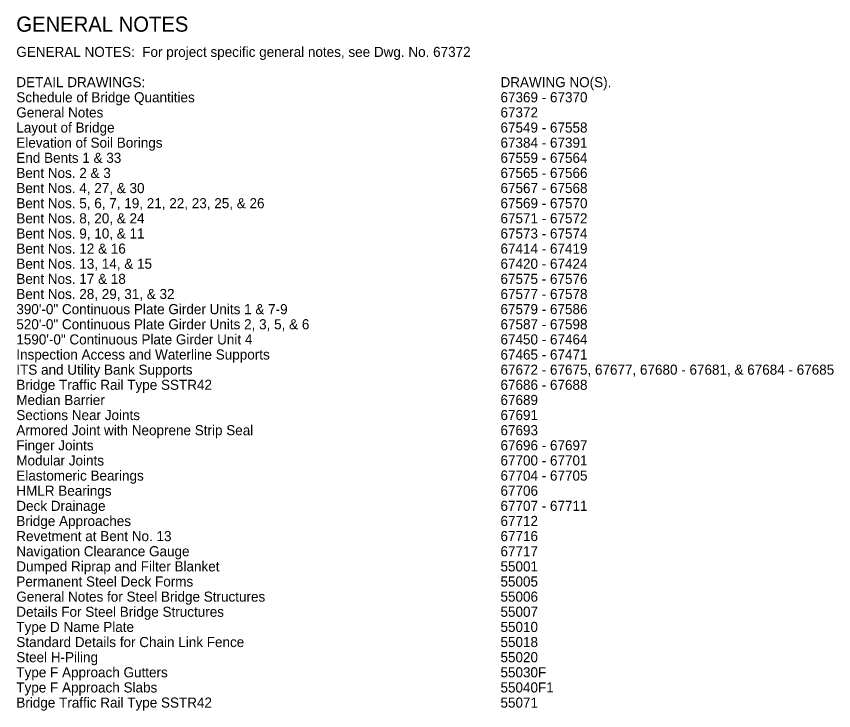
# Model space of a CAD drawing. Extents: x 0.06 to 1.36, y 0.04 to 0.87.
# Drawn here: x 0.0907 to 0.4959, y 0.5215 to 0.8656 of the extents above; entities that cross this region are included whole.
import ezdxf

# ---------------------------------------------------------------- set-up
doc = ezdxf.new("R2010")
doc.units = 0
doc.layers.add('B_Boring Annot', color=7, linetype='Continuous')
doc.layers.add('R_ROW', color=7, linetype='Continuous')

msp = doc.modelspace()

# ---------------------------------------------------------------- texts
at = {"layer": 'B_Boring Annot'}
for s, p in [('GENERAL NOTES:  For project specific general notes, see Dwg. No. 67372', (0.09071, 0.84552)), ('DETAIL DRAWINGS:', (0.09071, 0.83052)), ('DRAWING NO(S).', (0.33071, 0.83052)), ('Schedule of Bridge Quantities', (0.09071, 0.82302)), ('67369 - 67370', (0.33071, 0.82302)), ('General Notes', (0.09071, 0.81552)), ('67372', (0.33071, 0.81552)), ('Layout of Bridge', (0.09071, 0.80802)), ('67549 - 67558', (0.33071, 0.80802)), ('Elevation of Soil Borings', (0.09071, 0.80052)), ('67384 - 67391', (0.33071, 0.80052)), ('End Bents 1 & 33', (0.09071, 0.79302)), ('67559 - 67564', (0.33071, 0.79302)), ('Bent Nos. 2 & 3', (0.09071, 0.78552)), ('67565 - 67566', (0.33071, 0.78552)), ('Bent Nos. 4, 27, & 30', (0.09071, 0.77802)), ('67567 - 67568', (0.33071, 0.77802)), ('Bent Nos. 5, 6, 7, 19, 21, 22, 23, 25, & 26', (0.09071, 0.77052)), ('67569 - 67570', (0.33071, 0.77052)), ('Bent Nos. 8, 20, & 24', (0.09071, 0.76302)), ('67571 - 67572', (0.33071, 0.76302)), ('Bent Nos. 9, 10, & 11', (0.09071, 0.75552)), ('67573 - 67574', (0.33071, 0.75552)), ('Bent Nos. 12 & 16', (0.09071, 0.74802)), ('67414 - 67419', (0.33071, 0.74802)), ('Bent Nos. 13, 14, & 15', (0.09071, 0.74052)), ('67420 - 67424', (0.33071, 0.74052)), ('Bent Nos. 17 & 18', (0.09071, 0.73302)), ('67575 - 67576', (0.33071, 0.73302)), ('Bent Nos. 28, 29, 31, & 32', (0.09071, 0.72552)), ('67577 - 67578', (0.33071, 0.72552)), ('390\'-0" Continuous Plate Girder Units 1 & 7-9', (0.09071, 0.71802)), ('67579 - 67586', (0.33071, 0.71802)), ('520\'-0" Continuous Plate Girder Units 2, 3, 5, & 6', (0.09071, 0.71052)), ('67587 - 67598', (0.33071, 0.71052)), ('1590\'-0" Continuous Plate Girder Unit 4', (0.09071, 0.70302)), ('67450 - 67464', (0.33071, 0.70302)), ('Inspection Access and Waterline Supports', (0.09071, 0.69552)), ('67465 - 67471', (0.33071, 0.69552)), ('ITS and Utility Bank Supports', (0.09071, 0.68802)), ('67672 - 67675, 67677, 67680 - 67681, & 67684 - 67685', (0.33071, 0.68802)), ('Bridge Traffic Rail Type SSTR42', (0.09071, 0.68052)), ('67686 - 67688', (0.33071, 0.68052)), ('Median Barrier', (0.09071, 0.67302)), ('67689', (0.33071, 0.67302)), ('Sections Near Joints', (0.09071, 0.66552)), ('67691', (0.33071, 0.66552)), ('Armored Joint with Neoprene Strip Seal', (0.09071, 0.65802)), ('67693', (0.33071, 0.65802)), ('Finger Joints', (0.09071, 0.65052)), ('67696 - 67697', (0.33071, 0.65052)), ('Modular Joints', (0.09071, 0.64302)), ('67700 - 67701', (0.33071, 0.64302)), ('Elastomeric Bearings', (0.09071, 0.63552)), ('67704 - 67705', (0.33071, 0.63552)), ('HMLR Bearings', (0.09071, 0.62802)), ('67706', (0.33071, 0.62802)), ('Deck Drainage', (0.09071, 0.62052)), ('67707 - 67711', (0.33071, 0.62052)), ('Bridge Approaches', (0.09071, 0.61302)), ('67712', (0.33071, 0.61302)), ('Revetment at Bent No. 13', (0.09071, 0.60552)), ('67716', (0.33071, 0.60552)), ('Navigation Clearance Gauge', (0.09071, 0.59802)), ('67717', (0.33071, 0.59802)), ('Dumped Riprap and Filter Blanket', (0.09071, 0.59052)), ('55001', (0.33071, 0.59052)), ('Permanent Steel Deck Forms', (0.09071, 0.58302)), ('55005', (0.33071, 0.58302)), ('General Notes for Steel Bridge Structures', (0.09071, 0.57552)), ('55006', (0.33071, 0.57552)), ('Details For Steel Bridge Structures', (0.09071, 0.56802)), ('55007', (0.33071, 0.56802)), ('Type D Name Plate', (0.09071, 0.56052)), ('55010', (0.33071, 0.56052)), ('Standard Details for Chain Link Fence', (0.09071, 0.55302)), ('55018', (0.33071, 0.55302)), ('Steel H-Piling', (0.09071, 0.54552)), ('55020', (0.33071, 0.54552)), ('Type F Approach Gutters', (0.09071, 0.53802)), ('55030F', (0.33071, 0.53802)), ('Type F Approach Slabs', (0.09071, 0.53052)), ('55040F1', (0.33071, 0.53052)), ('Bridge Traffic Rail Type SSTR42', (0.09071, 0.52302)), ('55071', (0.33071, 0.52302))]:
    msp.add_text(s, height=0.005, dxfattribs=at).set_placement(p)
at = {"layer": 'R_ROW'}
msp.add_text('GENERAL NOTES', height=0.0075, dxfattribs=at).set_placement((0.09071, 0.85802))

doc.saveas('drawing.dxf')
